(* Logix 5000 project; controller CompactLogix vendor 1 type 14 code 77 rev 13.15; software revision 13.03 *)

TASK MainTask (continuous, watchdog 500 ms) : MainProgram

MODULES
   Controller : vendor 1 type 14 code 77 (CompactLogixL32EController 0, rev 13.15)
      LocalENB : 1769-L32E Ethernet Port (CompactLogixL32Ethernet 1, Ethernet 192.168.10.210, rev 13.1)
      Local : CompactBus (CompactVirtualAdapter 3, rev 13.1, Input RPI 2 ms)
         DPM : 1769-MODULE (Compact 1, rev 1.1, Output RPI 2 ms)
END_MODULES

TYPE DDLM_GLOBAL_CONTROL_CONFIRM :
STRUCT
   Reserved1 : INT;
   Reserved2 : INT;
   Answer : SINT;
   Failure : SINT;
   Reserved3 : INT;
   DeviceAdr : SINT;
END_STRUCT
END_TYPE

TYPE DDLM_GLOBAL_CONTROL_REQUEST :
STRUCT
   Reserved1 : INT;
   Reserved2 : INT;
   Reserved3 : INT;
   Command : SINT;
   Reserved4 : SINT;
   DeviceAdr : SINT;
   ConrolCommand : SINT;
   GroupSelect : SINT;
END_STRUCT
END_TYPE

TYPE DDLM_SET_PARAMETER_CONFIRM :
STRUCT
   Reserved1 : INT;
   Reserved2 : INT;
   Answer : SINT;
   Failure : SINT;
   Reserved3 : INT;
   DeviceAdr : SINT;
END_STRUCT
END_TYPE

TYPE DDLM_SET_PARAMETER_REQUEST :
STRUCT
   Reserved1 : INT;
   Reserved2 : INT;
   Reserved3 : INT;
   Command : SINT;
   Reserved4 : SINT;
   UsrPrm : SINT[234];
END_STRUCT
END_TYPE

TYPE DDLM_SLAVE_DIAGNOSTIC_CONFIRM :
STRUCT
   Reserved1 : INT;
   Reserved2 : INT;
   Answer : SINT;
   Failure : SINT;
   Reserved3 : INT;
   DeviceAdr : SINT;
   DataArea : SINT;
   DataAdr : INT;
   DataIdx : SINT;
   DataCnt : SINT;
   DataType : SINT;
   Function : SINT;
   StationState_1 : SINT;
   StationState_2 : SINT;
   StationState_3 : SINT;
   MasterAddress : SINT;
   IdentNumber : INT;
   Reserved4 : INT;
   ExtDiag : SINT[100];
END_STRUCT
END_TYPE

TYPE DDLM_SLAVE_DIAGNOSTIC_REQUEST :
STRUCT
   Reserved1 : INT;
   Reserved2 : INT;
   Reserved3 : INT;
   Command : SINT;
   Reserved4 : SINT;
   DeviceAdr : SINT;
   DataArea : SINT;
   DataAdr : INT;
   DataIdx : SINT;
   DataCnt : SINT;
   DataType : SINT;
   Function : SINT;
END_STRUCT
END_TYPE

TYPE DPM_DEV_COMMAND_REGISTER :   // Device Command Register
STRUCT
   Reserved0 : BOOL;   // Reserved
   Reserved1 : BOOL;   // Reserved
   Reserved2 : BOOL;   // Reserved
   Reserved3 : BOOL;   // Reserved
   Reserved4 : BOOL;   // Reserved
   NRdy : BOOL;   // Application Not Ready
   Init : BOOL;   // Init ( Warm boot )
   Reset : BOOL;   // Reset ( Cold boot )
   HsReq0 : BOOL;   // Slave Diag Request
   HsReq1 : BOOL;   // Global Control Request
   HsReq2 : BOOL;   // Reserved
   HsReq3 : BOOL;   // Reserved
   HsReq4 : BOOL;   // Reserved
   HsReq5 : BOOL;   // Reserved
   HsReq6 : BOOL;   // Reserved
   HsReq7 : BOOL;   // Reserved
   Reserved5 : SINT;   // Reserved
   Reserved6 : SINT;   // Reserved
END_STRUCT
END_TYPE

TYPE DPM_DEV_STATUS_REGISTER :   // Device Status Register
STRUCT
   Reserved0 : BOOL;
   Reserved1 : BOOL;
   Reserved2 : BOOL;
   Reserved3 : BOOL;
   Reserved4 : BOOL;
   Com : BOOL;   // Communication
   Run : BOOL;   // Running
   Rdy : BOOL;   // Ready
   HsAck0 : BOOL;   // Slave Diag Acknowledge
   HsAck1 : BOOL;   // Global Control Acknowledge
   HsAck2 : BOOL;
   HsAck3 : BOOL;
   HsAck4 : BOOL;
   HsAck5 : BOOL;
   HsAck6 : BOOL;
   HsAck7 : BOOL;
   Reserved5 : SINT;
   Reserved6 : SINT;
END_STRUCT
END_TYPE

TYPE DPM_DPV1_ALARM_INDICATION :   // DPV1 Alarm Indication
STRUCT
   AlarmIndication : BOOL;   // Indicates an alarm
   Reserved1 : BOOL;
   Reserved2 : BOOL;
   Reserved3 : BOOL;
   Reserved4 : BOOL;
   Reserved5 : BOOL;
   Reserved6 : BOOL;
   AlarmOverrun : BOOL;   // Overflow of the modules internal alarm buffer
   AlarmCnt : SINT;   // Alarm indication counter
   RemoteAddress : SINT;   // Address of Slave with Alarm
   Slot : SINT;   // Slot Number
   Sequence : SINT;   // Sequence Number
   AlarmType : SINT;   // Alarm Type
   AlarmSpec : SINT;   // Alarm Specification
   Reserved7 : SINT;
END_STRUCT
END_TYPE

TYPE DPM_FW_REVISION :   // Firmware Major/Minor Revision
STRUCT
   FwMinor : SINT;   // Firmware Minor Revison
   FwMajor : SINT;   // Firmware Major Revison
   Reserved : INT;   // Reserved
END_STRUCT
END_TYPE

TYPE DPM_GLOBAL_CONTROL_COMMAND :   // Global Control Command
STRUCT
   SlaveAddress : SINT;   // Slave Address
   ControlCommand : SINT;   // Control Command to be send
   GroupSelect : SINT;   // Group Select
   Reserved1 : SINT;
END_STRUCT
END_TYPE

TYPE DPM_GLOBAL_STATE_FIELD :   // PROFIBUS Master Global State Field
STRUCT
   Ctrl : BOOL;   // Control error
   Aclr : BOOL;   // Auto clear error
   Nexc : BOOL;   // Non exchange error
   Fat : BOOL;   // Fatal error
   Eve : BOOL;   // Event error
   NRdy : BOOL;   // Host not ready notification
   Tout : BOOL;   // Timeout
   Reserved1 : BOOL;   // Reserved
   DPM_State : SINT;   // Master main state
   Err_rem_adr : SINT;   // Faulty remote address
   Err_event : SINT;   // Error Number
   Bus_err_cnt : INT;   // Heavy bus error counter
   Time_out_cnt : INT;   // Number of rejected PROFIBUS Telegr.
   Reserved : SINT[8];   // Reserved
   Sl_cfg : BOOL[128];   // Slave Config
   Sl_state : BOOL[128];   // Slave State
   Sl_diag : BOOL[128];   // Slave Diag
END_STRUCT
END_TYPE

TYPE DPM_INPUT_ARRAY :
STRUCT
   DevStaReg : DPM_DEV_STATUS_REGISTER;
   FwRev : DPM_FW_REVISION;
   GlobStateField : DPM_GLOBAL_STATE_FIELD;
   SlaveDiag : DPM_SLAVE_DIAG_DATA;
   AlarmInd : DPM_DPV1_ALARM_INDICATION;
   InputData : SINT[408];   // PROFIBUS Input data.
END_STRUCT
END_TYPE

TYPE DPM_OUTPUT_ARRAY :
STRUCT
   DevCmdReg : DPM_DEV_COMMAND_REGISTER;
   DiagReqAdr : DPM_SLAVE_DIAG_COMMAND;
   GlobCtrl : DPM_GLOBAL_CONTROL_COMMAND;
   Reserved : SINT[4];
   OutputData : SINT[480];   // PROFIBUS Output data.
END_STRUCT
END_TYPE

TYPE DPM_SLAVE_DIAG_COMMAND :   // Requested address for SlaveDiagnostics
STRUCT
   SlaveAddress : SINT;
   DiagMode : SINT;
   Reserved1 : SINT;
   Reserved2 : SINT;
END_STRUCT
END_TYPE

TYPE DPM_SLAVE_DIAG_DATA :   // Slave standard diagnostic data according to PROFIBUS norm.
STRUCT
   SlaveAddress : SINT;   // Slave address
   DiagFailure : SINT;   // Slave Diag Failure
   Sta1_StationNotExist : BOOL;   // No response
   Sta1_StationNotReady : BOOL;   // Station not ready
   Sta1_CfgFault : BOOL;   // Configuration faulty
   Sta1_ExtDiag : BOOL;   // Extended diagnostic
   Sta1_NotSupp : BOOL;   // Sync,Freeze not supported
   Sta1_InvalidResponse : BOOL;   // Response faulty
   Sta1_PrmFault : BOOL;   // Parameters faulty
   Sta1_MasterLock : BOOL;   // Locked by a master
   Sta2_PrmReq : BOOL;   // Request new parameter
   Sta2_StatDiag : BOOL;   // Static diagnostic
   Sta2_Slave : BOOL;   // Set to 1 by a slave
   Sta2_Watchdog : BOOL;   // Watchdog ON/OFF
   Sta2_FreezeMode : BOOL;   // Freeze mode active
   Sta2_SyncMode : BOOL;   // Sync mode active
   Sta2_Reserved : BOOL;   // Reserved
   Sta2_Deactivated : BOOL;   // Slave deactivated
   Sta3_Reserved0 : BOOL;   // Reserved
   Sta3_Reserved1 : BOOL;   // Reserved
   Sta3_Reserved2 : BOOL;   // Reserved
   Sta3_Reserved3 : BOOL;   // Reserved
   Sta3_Reserved4 : BOOL;   // Reserved
   Sta3_Reserved5 : BOOL;   // Reserved
   Sta3_Reserved6 : BOOL;   // Reserved
   Sta3_ExtDiagOverflow : BOOL;   // Extended diagnostic overflow
   MasterAddress : SINT;   // Corresponding master address
   IdentNumber : INT;   // PROFIBUS Ident number
END_STRUCT
END_TYPE

TYPE MSAC1_READ_CONFIRM :   // DPV1 Read Confirmation
STRUCT
   Reserved1 : INT;
   Reserved2 : INT;
   Answer : SINT;
   Failure : SINT;
   Reserved3 : INT;
   DeciceAdr : SINT;
   DataArea : SINT;
   DataAdr : INT;
   DataIdx : SINT;
   DataCnt : SINT;
   DataType : SINT;
   Function : SINT;
   Data : SINT[240];
END_STRUCT
END_TYPE

TYPE MSAC1_READ_REQUEST :   // DPV1 Read Request
STRUCT
   Reserved1 : INT;
   Reserved2 : INT;
   Reserved3 : INT;
   Command : SINT;
   Reserved4 : SINT;
   DeviceAdr : SINT;
   DataArea : SINT;
   DataAdr : INT;
   DataIdx : SINT;
   DataCnt : SINT;
   DataType : SINT;
   Function : SINT;
END_STRUCT
END_TYPE

TYPE MSAC1_WRITE_CONFIRM :   // DPV1 Write Confirmation
STRUCT
   Reserved1 : INT;
   Reserved2 : INT;
   Answer : SINT;
   Failure : SINT;
   Reserved3 : INT;
   DeciceAdr : SINT;
   DataArea : SINT;
   DataAdr : INT;
   DataIdx : SINT;
   DataCnt : SINT;
   DataType : SINT;
   Function : SINT;
   ErrorCode1 : SINT;
   ErrorCode2 : SINT;
END_STRUCT
END_TYPE

TYPE MSAC1_WRITE_REQUEST :   // DPV1 Write Request
STRUCT
   Reserved1 : INT;
   Reserved2 : INT;
   Reserved3 : INT;
   Command : SINT;
   Reserved4 : SINT;
   DeviceAdr : SINT;
   DataArea : SINT;
   DataAdr : INT;
   DataIdx : SINT;
   DataCnt : SINT;
   DataType : SINT;
   Function : SINT;
   data : SINT[240];
END_STRUCT
END_TYPE

TYPE MSAL1M_ALARM_CONFIRM :
STRUCT
   Reserved1 : INT;
   Reserved2 : INT;
   Answer : SINT;
   Failure : SINT;
   Reserved3 : INT;
   SlaveAdr : SINT;
   SlotNum : SINT;
   SeqNum : SINT;
   AlarmType : SINT;
   AlarmSpec : SINT;
   Reserved4 : SINT;
END_STRUCT
END_TYPE

TYPE MSAL1M_ALARM_RESPONSE :
STRUCT
   Reserved1 : INT;
   Reserved2 : INT;
   Reserved3 : INT;
   Command : SINT;
   Reserved4 : SINT;
   SlaveAdr : SINT;
   SlotNum : SINT;
   SeqNum : SINT;
   AlarmType : SINT;
   AlarmSpec : SINT;
   Reserved5 : SINT;
END_STRUCT
END_TYPE

VAR_GLOBAL   (* controller tags *)
   AlarmCnf : MSAL1M_ALARM_CONFIRM := (Answer := 18, SlaveAdr := 2, SlotNum := -122, SeqNum := 6, AlarmType := 59, AlarmSpec := 6);
   AlarmIndCounter : SINT;
   AlarmReceiveCounter : INT;   // Alarm Counter
   AlarmResErr : BOOL;
   AlarmRsp : MSAL1M_ALARM_RESPONSE := (Command := 18);
   AlarmRspMsg : MESSAGE;   // Alarm Response Message
        MessageParameters(ServiceCode := 16#0064, LocalElement := AlarmRsp, DestinationTag := AlarmCnf, ...)
   DoDDLMGlblCtrl : BOOL;
   DoDDLMSetPrm : BOOL;
   DoDDLMSlaveDiag : BOOL;
   DoDPV1AlarmRsp : BOOL;
   DoDPV1ReadReq : BOOL;
   DoDPV1WriteReq : BOOL;
   DpmInputArray : DPM_INPUT_ARRAY;
   DpmOutputArray : DPM_OUTPUT_ARRAY;
   GlbCtrlCnf : DDLM_GLOBAL_CONTROL_CONFIRM := (Answer := 70, DeviceAdr := 2);   // Global Control Confirmation
   GlbCtrlMsg : MESSAGE;   // Global Control Message
        MessageParameters(ServiceCode := 16#0064, LocalElement := GlbCtrlReq, DestinationTag := GlbCtrlCnf, ...)
   GlbCtrlReq : DDLM_GLOBAL_CONTROL_REQUEST := (Command := 70, DeviceAdr := 2, ConrolCommand := 2#0000_1000);   // Global Control Request
        .COMMAND   // Global Control Request
   MainInitDone : BOOL;
   ReadCnf : MSAC1_READ_CONFIRM := (Answer := 17, DeciceAdr := 2, DataAdr := 1, DataIdx := 1, DataCnt := 2, DataType := 10, Function := 1, Data[0] := 1, Data[1] := 2);   // Read Confimation
   ReadReq : MSAC1_READ_REQUEST := (Command := 17, DeviceAdr := 2, DataAdr := 1, DataIdx := 1, DataCnt := 2, DataType := 10, Function := 1);   // Read Request
   ReadReqMsg : MESSAGE;   // Slave Read Request Message
        .EN   // Slave Read Request Message
        MessageParameters(ServiceCode := 16#0064, LocalElement := ReadReq, DestinationTag := ReadCnf, ...)
   SetPrmCnf : DDLM_SET_PARAMETER_CONFIRM := (Answer := 74, DeviceAdr := 2);   // Set parameter confirmation
   SetPrmReq : DDLM_SET_PARAMETER_REQUEST := (Command := 74, UsrPrm[0] := 2);   // Set parameter request
   SetPrmReqMsg : MESSAGE;
        MessageParameters(ServiceCode := 16#0064, LocalElement := SetPrmReq, DestinationTag := SetPrmCnf, ...)
   SlaveAddress : SINT;   // Slave address used by several CIP messages
   SlaveDiagCnf : DDLM_SLAVE_DIAGNOSTIC_CONFIRM := (Answer := 66, DeviceAdr := 2, DataCnt := 6, Function := 1, StationState_1 := 2#0000_1000, StationState_2 := 2#0000_1100, MasterAddress := 1, IdentNumber := 16#0475, ExtDiag[0] := 18, ExtDiag[1] := 59, ExtDiag[2] := -122, ExtDiag[3] := 54, ExtDiag[4] := 77, ExtDiag[5] := 65, ExtDiag[6] := 89, ExtDiag[7] := 68, ExtDiag[8] := 65, ExtDiag[9] := 89, ExtDiag[10] := 44, ExtDiag[11] := 32, ExtDiag[12] := 77, ExtDiag[13] := 65, ExtDiag[14] := 89, ExtDiag[15] := 68, ExtDiag[16] := 65, ExtDiag[17] := 89);   // Slave Diag Confirmation
   SlaveDiagMsg : MESSAGE;   // Slave Diag Message
        .EN   // Slave Diag Message
        MessageParameters(ServiceCode := 16#0064, LocalElement := SlaveDiagReq, DestinationTag := SlaveDiagCnf, ...)
   SlaveDiagReq : DDLM_SLAVE_DIAGNOSTIC_REQUEST := (Command := 66, DeviceAdr := 2, Function := 1);   // Slave Diag Request
   WriteCnf : MSAC1_WRITE_CONFIRM := (Answer := 17, DeciceAdr := 2, DataAdr := 1, DataIdx := 1, DataCnt := 2, DataType := 10, Function := 2);   // Slave Write Confirmation
   WriteReq : MSAC1_WRITE_REQUEST := (Command := 17, DeviceAdr := 2, DataAdr := 1, DataIdx := 1, DataCnt := 2, DataType := 10, Function := 2, data[0] := 85, data[1] := 17);   // Slave Write Request
   WriteReqMsg : MESSAGE;   // Slave Write Request Message
        .EN   // Slave Write Request Message
        MessageParameters(ServiceCode := 16#0064, LocalElement := WriteReq, DestinationTag := WriteCnf, ...)
END_VAR

PROGRAM MainProgram   (* routine attr 65 MainRoutine *)

ROUTINE AlarmHandler   (* ladder *)
// Alarm Handler
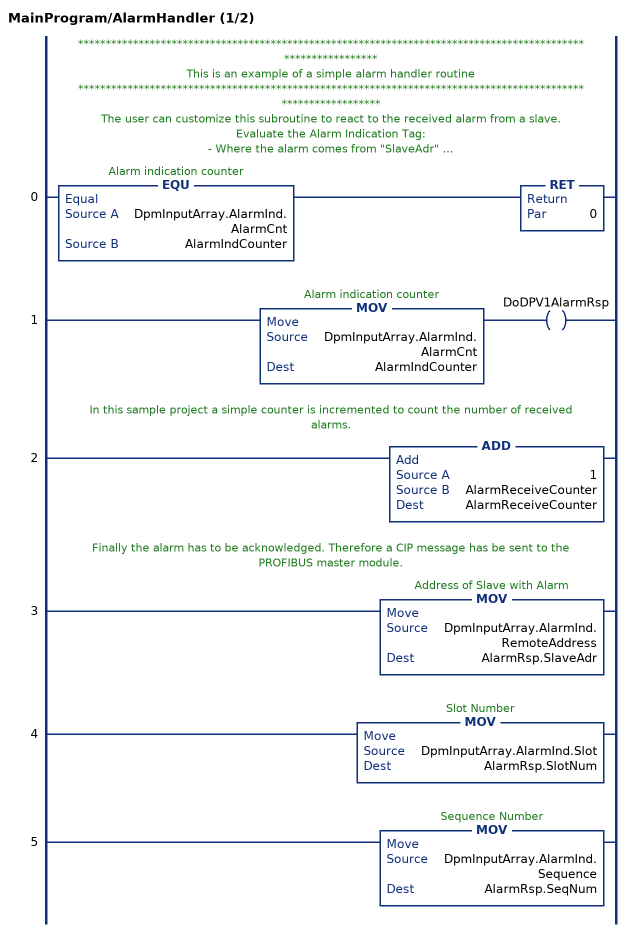
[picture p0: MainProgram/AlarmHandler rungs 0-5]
   // *************************************************************************************************************
   // This is an example of a simple alarm handler routine
   // **************************************************************************************************************
   // The user can customize this subroutine to react to the received alarm from a slave.
   // Evaluate the Alarm Indication Tag:
   //  - Where the alarm comes from "SlaveAdr" ?
   // -  What kind of alarm is it  "AlarmType" ?
   // ect. ....
   0: EQU(DpmInputArray.AlarmInd.AlarmCnt,AlarmIndCounter)RET(0);
   1: MOV(DpmInputArray.AlarmInd.AlarmCnt,AlarmIndCounter)OTE(DoDPV1AlarmRsp);
   // In this sample project a simple counter is incremented to count the number of received alarms.
   2: ADD(1,AlarmReceiveCounter,AlarmReceiveCounter);
   // Finally the alarm has to be acknowledged. Therefore a CIP message has be sent to the PROFIBUS master module.
   3: MOV(DpmInputArray.AlarmInd.RemoteAddress,AlarmRsp.SlaveAdr);
   4: MOV(DpmInputArray.AlarmInd.Slot,AlarmRsp.SlotNum);
   5: MOV(DpmInputArray.AlarmInd.Sequence,AlarmRsp.SeqNum);
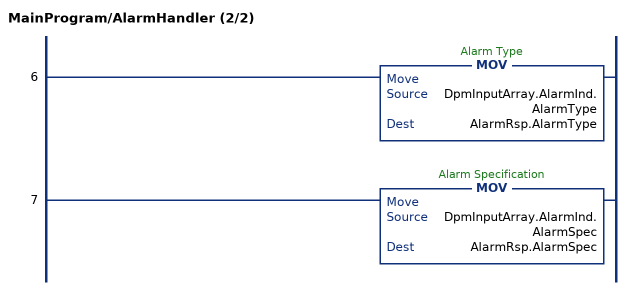
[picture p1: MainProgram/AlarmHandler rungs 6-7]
   6: MOV(DpmInputArray.AlarmInd.AlarmType,AlarmRsp.AlarmType);
   7: MOV(DpmInputArray.AlarmInd.AlarmSpec,AlarmRsp.AlarmSpec);
END_ROUTINE

ROUTINE Init_AlarmResMsg   (* ladder *)
// Init Alarm Response Message
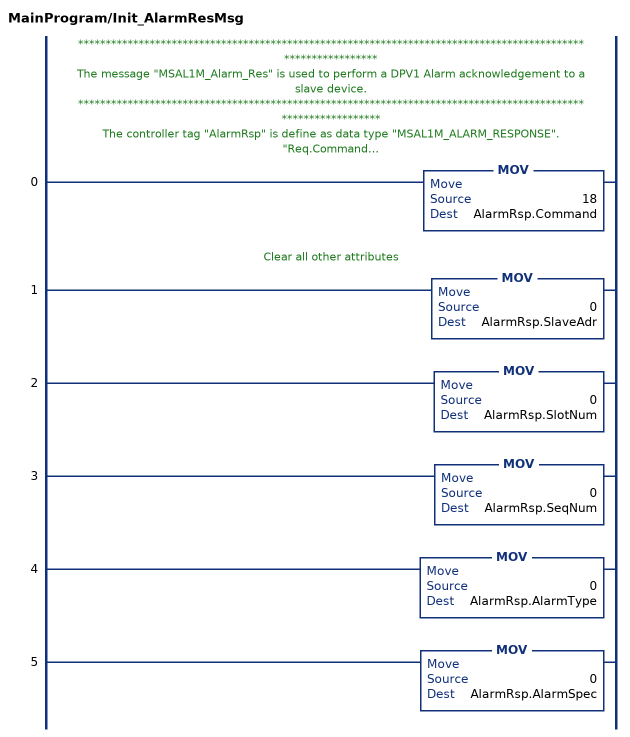
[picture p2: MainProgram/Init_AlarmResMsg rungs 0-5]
   // *************************************************************************************************************
   // The message "MSAL1M_Alarm_Res" is used to perform a DPV1 Alarm acknowledgement to a slave device.
   // **************************************************************************************************************
   // The controller tag "AlarmRsp" is define as data type "MSAL1M_ALARM_RESPONSE".
   // "Req.Command"
   // Setup "Req.Command" to 18. This is the command for "MSAL1M_Alarm_Res".
   0: MOV(18,AlarmRsp.Command);
   // Clear all other attributes
   1: MOV(0,AlarmRsp.SlaveAdr);
   2: MOV(0,AlarmRsp.SlotNum);
   3: MOV(0,AlarmRsp.SeqNum);
   4: MOV(0,AlarmRsp.AlarmType);
   5: MOV(0,AlarmRsp.AlarmSpec);
END_ROUTINE

ROUTINE Init_GlobalControlMsg   (* ladder *)
// Init Global Control Message
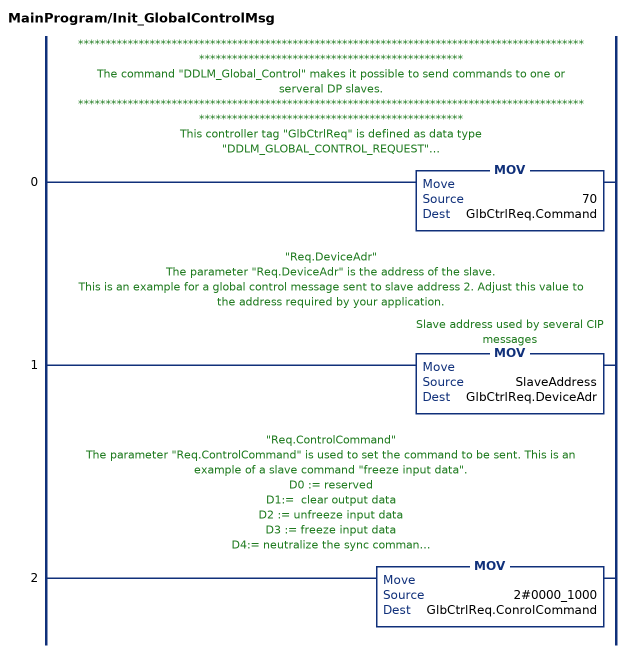
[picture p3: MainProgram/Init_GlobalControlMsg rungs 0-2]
   // ********************************************************************************************************************************************
   // The command "DDLM_Global_Control" makes it possible to send commands to one or serveral DP slaves.
   // ********************************************************************************************************************************************
   // This controller tag "GlbCtrlReq" is defined as data type "DDLM_GLOBAL_CONTROL_REQUEST".
   // "Req.Command"
   // Setup "Req.Command" to 70. This is the command for "DDLM_Global_Control".
   0: MOV(70,GlbCtrlReq.Command);
   // "Req.DeviceAdr"
   // The parameter "Req.DeviceAdr" is the address of the slave.
   // This is an example for a global control message sent to slave address 2. Adjust this value to the address required by your application.
   1: MOV(SlaveAddress,GlbCtrlReq.DeviceAdr);
   // "Req.ControlCommand"
   // The parameter "Req.ControlCommand" is used to set the command to be sent. This is an example of a slave command "freeze input data".
   // D0 := reserved
   // D1:=  clear output data
   // D2 := unfreeze input data
   // D3 := freeze input data
   // D4:= neutralize the sync command
   // D5 := freeze output data, till sync command is canceled
   // D6 := reserved
   // D7 := reserved
   2: MOV(2#0000_1000,GlbCtrlReq.ConrolCommand);
END_ROUTINE

ROUTINE Init_GlobalVariables   (* ladder *)
// Initialization of global variables which are used in several program parts
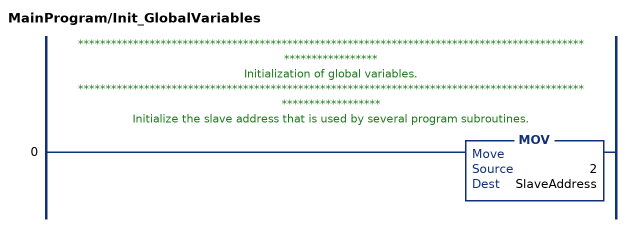
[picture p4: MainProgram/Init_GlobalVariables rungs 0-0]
   // *************************************************************************************************************
   // Initialization of global variables.
   // **************************************************************************************************************
   // Initialize the slave address that is used by several program subroutines.
   0: MOV(2,SlaveAddress);
END_ROUTINE

ROUTINE Init_ReadReqMsg   (* ladder *)
// Init Read Request Message
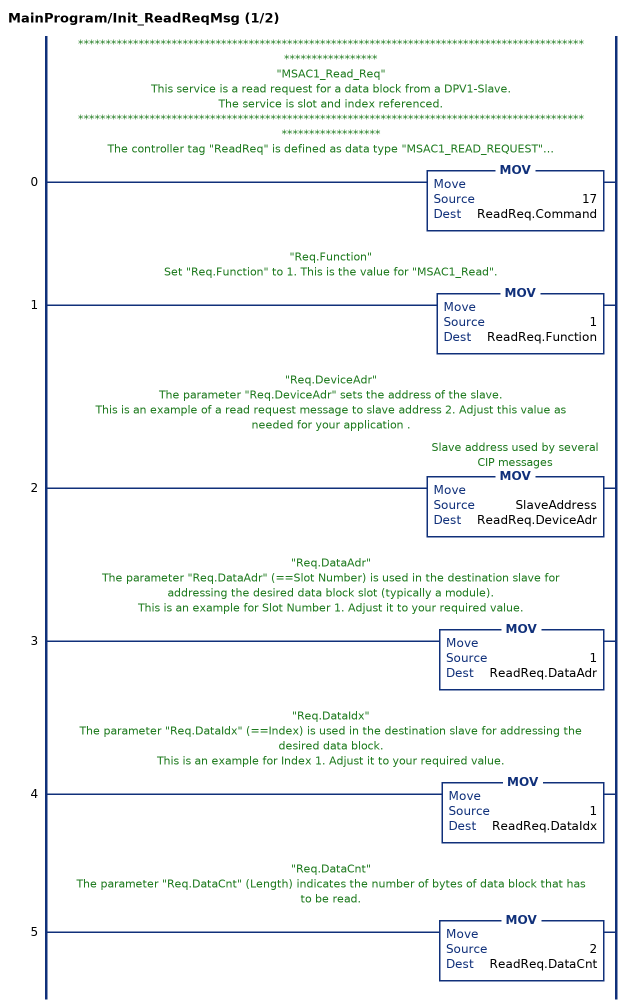
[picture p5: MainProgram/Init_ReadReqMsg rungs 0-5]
   // *************************************************************************************************************
   // "MSAC1_Read_Req"
   // This service is a read request for a data block from a DPV1-Slave.
   // The service is slot and index referenced.
   // **************************************************************************************************************
   // The controller tag "ReadReq" is defined as data type "MSAC1_READ_REQUEST".
   // "Req.Command"
   // Set "Req.Command" to 17. This is the command for "MSAC1_Read" and  "MSAC1_Write
   0: MOV(17,ReadReq.Command);
   // "Req.Function"
   // Set "Req.Function" to 1. This is the value for "MSAC1_Read".
   1: MOV(1,ReadReq.Function);
   // "Req.DeviceAdr"
   // The parameter "Req.DeviceAdr" sets the address of the slave.
   // This is an example of a read request message to slave address 2. Adjust this value as needed for your application .
   2: MOV(SlaveAddress,ReadReq.DeviceAdr);
   // "Req.DataAdr"
   // The parameter "Req.DataAdr" (==Slot Number) is used in the destination slave for addressing the desired data block slot (typically a module).
   // This is an example for Slot Number 1. Adjust it to your required value.
   3: MOV(1,ReadReq.DataAdr);
   // "Req.DataIdx"
   // The parameter "Req.DataIdx" (==Index) is used in the destination slave for addressing the desired data block.
   // This is an example for Index 1. Adjust it to your required value.
   4: MOV(1,ReadReq.DataIdx);
   // "Req.DataCnt"
   // The parameter "Req.DataCnt" (Length) indicates the number of bytes of data block that has to be read.
   5: MOV(2,ReadReq.DataCnt);
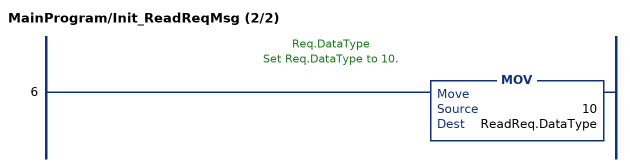
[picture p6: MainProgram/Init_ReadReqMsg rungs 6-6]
   // Req.DataType
   // Set Req.DataType to 10.
   6: MOV(10,ReadReq.DataType);
END_ROUTINE

ROUTINE Init_SetParameterMsg   (* ladder *)
// Init Set Parameter Message
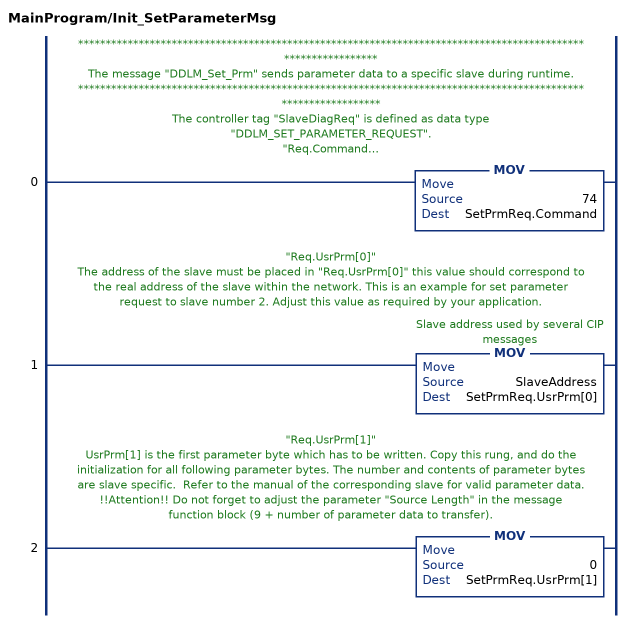
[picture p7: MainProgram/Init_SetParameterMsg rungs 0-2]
   // *************************************************************************************************************
   // The message "DDLM_Set_Prm" sends parameter data to a specific slave during runtime.
   // **************************************************************************************************************
   // The controller tag "SlaveDiagReq" is defined as data type "DDLM_SET_PARAMETER_REQUEST".
   // "Req.Command"
   // Set "Req.Command" to 74. This is the command for "DDLM_Set_Prm"
   0: MOV(74,SetPrmReq.Command);
   // "Req.UsrPrm[0]"
   // The address of the slave must be placed in "Req.UsrPrm[0]" this value should correspond to the real address of the slave within the network. This is an example for set parameter request to slave number 2. Adjust this value as required by your application.
   1: MOV(SlaveAddress,SetPrmReq.UsrPrm[0]);
   // "Req.UsrPrm[1]"
   // UsrPrm[1] is the first parameter byte which has to be written. Copy this rung, and do the initialization for all following parameter bytes. The number and contents of parameter bytes are slave specific.  Refer to the manual of the corresponding slave for valid parameter data.
   // !!Attention!! Do not forget to adjust the parameter "Source Length" in the message function block (9 + number of parameter data to transfer).
   2: MOV(0,SetPrmReq.UsrPrm[1]);
END_ROUTINE

ROUTINE Init_SlaveDiagMsg   (* ladder *)
// Init Slave Diag Message
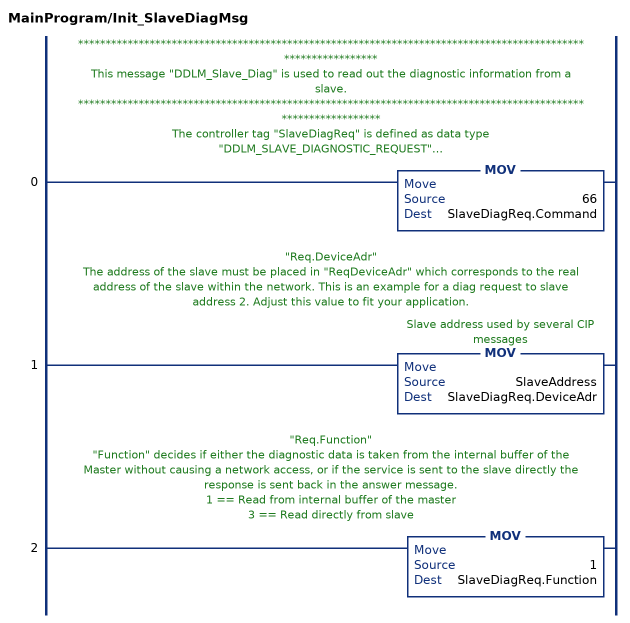
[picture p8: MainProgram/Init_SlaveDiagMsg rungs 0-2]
   // *************************************************************************************************************
   // This message "DDLM_Slave_Diag" is used to read out the diagnostic information from a slave.
   // **************************************************************************************************************
   // The controller tag "SlaveDiagReq" is defined as data type "DDLM_SLAVE_DIAGNOSTIC_REQUEST".
   // "Req.Command"
   // Set "Req.Command" to 66. This is the command for "DDLM_Slave_Dialg"
   0: MOV(66,SlaveDiagReq.Command);
   // "Req.DeviceAdr"
   // The address of the slave must be placed in "ReqDeviceAdr" which corresponds to the real address of the slave within the network. This is an example for a diag request to slave address 2. Adjust this value to fit your application.
   1: MOV(SlaveAddress,SlaveDiagReq.DeviceAdr);
   // "Req.Function"
   // "Function" decides if either the diagnostic data is taken from the internal buffer of the Master without causing a network access, or if the service is sent to the slave directly the response is sent back in the answer message.
   // 1 == Read from internal buffer of the master
   // 3 == Read directly from slave
   2: MOV(1,SlaveDiagReq.Function);
END_ROUTINE

ROUTINE Init_WriteReqMsg   (* ladder *)
// Init Write Request Message
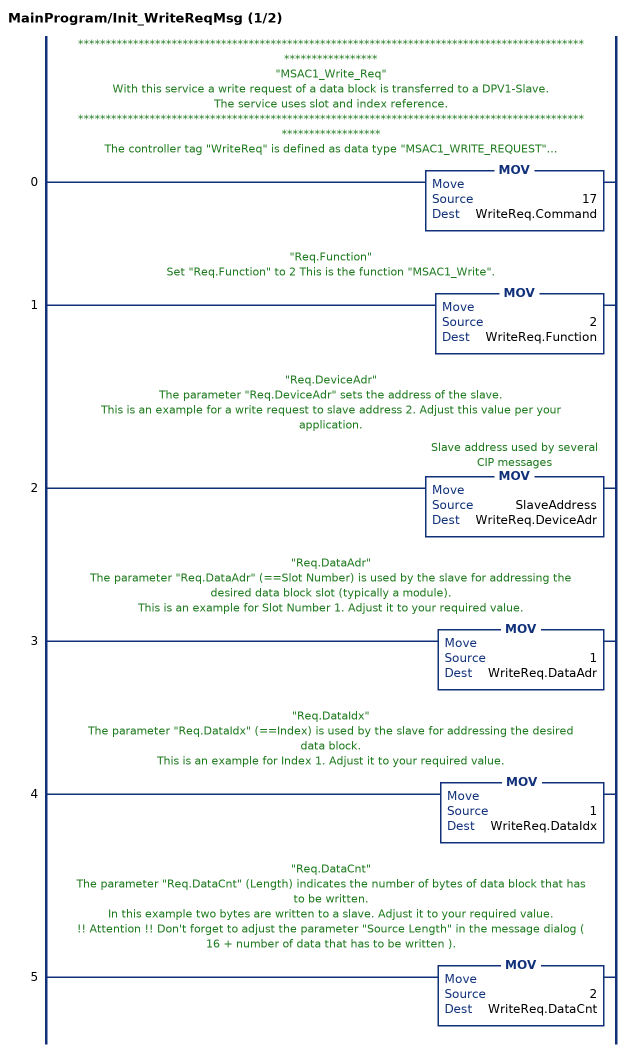
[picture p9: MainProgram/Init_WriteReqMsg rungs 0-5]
   // *************************************************************************************************************
   // "MSAC1_Write_Req"
   // With this service a write request of a data block is transferred to a DPV1-Slave.
   // The service uses slot and index reference.
   // **************************************************************************************************************
   // The controller tag "WriteReq" is defined as data type "MSAC1_WRITE_REQUEST".
   // "Req.Command"
   // Set "Req.Command" to 17. This is the command for "MSAC1_Write" and  "MSAC1_Read".
   0: MOV(17,WriteReq.Command);
   // "Req.Function"
   // Set "Req.Function" to 2 This is the function "MSAC1_Write".
   1: MOV(2,WriteReq.Function);
   // "Req.DeviceAdr"
   // The parameter "Req.DeviceAdr" sets the address of the slave.
   // This is an example for a write request to slave address 2. Adjust this value per your application.
   2: MOV(SlaveAddress,WriteReq.DeviceAdr);
   // "Req.DataAdr"
   // The parameter "Req.DataAdr" (==Slot Number) is used by the slave for addressing the desired data block slot (typically a module).
   // This is an example for Slot Number 1. Adjust it to your required value.
   3: MOV(1,WriteReq.DataAdr);
   // "Req.DataIdx"
   // The parameter "Req.DataIdx" (==Index) is used by the slave for addressing the desired data block.
   // This is an example for Index 1. Adjust it to your required value.
   4: MOV(1,WriteReq.DataIdx);
   // "Req.DataCnt"
   // The parameter "Req.DataCnt" (Length) indicates the number of bytes of data block that has to be written.
   // In this example two bytes are written to a slave. Adjust it to your required value.
   // !! Attention !! Don't forget to adjust the parameter "Source Length" in the message dialog ( 16 + number of data that has to be written ).
   5: MOV(2,WriteReq.DataCnt);
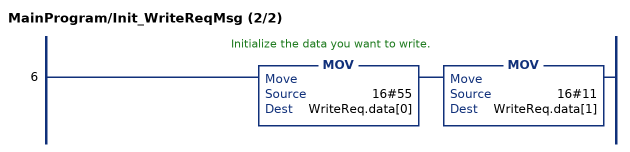
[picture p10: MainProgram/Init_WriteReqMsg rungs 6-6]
   // Initialize the data you want to write.
   6: MOV(16#55,WriteReq.data[0])MOV(16#11,WriteReq.data[1]);
END_ROUTINE

ROUTINE MainRoutine   (* ladder *)
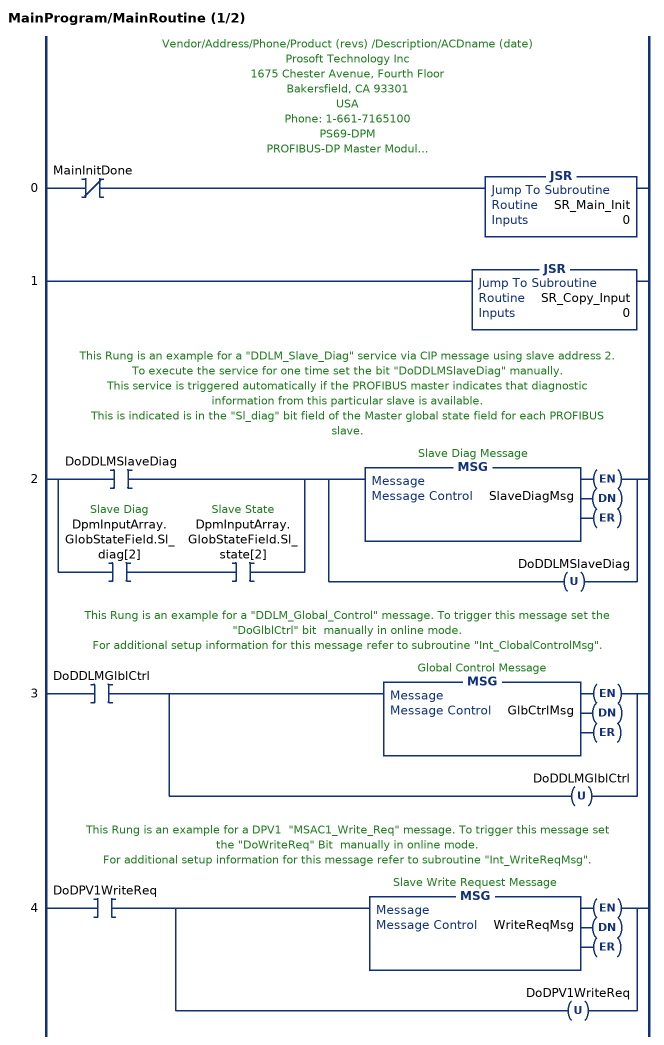
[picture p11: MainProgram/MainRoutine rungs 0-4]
   // Vendor/Address/Phone/Product (revs) /Description/ACDname (date)
   // Prosoft Technology Inc
   // 1675 Chester Avenue, Fourth Floor
   // Bakersfield, CA 93301
   // USA
   // Phone: 1-661-7165100
   // PS69-DPM
   // PROFIBUS-DP Master Module
   // PS69_DPM_messaging_L32E.ACD (Rev1.0) (07/28/05)
   // Although this program has been developed with great care and intensively tested,
   // Prosoft Technology Inc cannot guarantee the suitability of this program
   // for any purpose not confirmed by us in writing.
   // We reserve the right to modify our products and their specifications at any time in as far as this contributes to technical progress.
   // The version of the manual supplied with the program applies.
   // Guarantee claims shall be limited to the right to require rectification. Liability for any damages which may have arisen from the use of this program or its documentation shall be limited to cases of intent.
   // This program is a basic example RSLogix5000 project used for sending PROFIBUS messages to the communication module "PS69-DPM". This project provides an example for every supported PROFIBUS message by the module.
   // For detailed information about the these messages (functionality, parameters, error codes etc. ) refer to the module User Manual.
   // Rung 0 calls all init routines for one time, to initialize the PROFIBUS commands.
   0: XIO(MainInitDone)JSR(SR_Main_Init,0);
   1: JSR(SR_Copy_Input,0);
   // This Rung is an example for a "DDLM_Slave_Diag" service via CIP message using slave address 2.
   // To execute the service for one time set the bit "DoDDLMSlaveDiag" manually.
   // This service is triggered automatically if the PROFIBUS master indicates that diagnostic information from this particular slave is available.
   // This is indicated is in the "Sl_diag" bit field of the Master global state field for each PROFIBUS slave.
   2: [XIC(DoDDLMSlaveDiag) ,XIC(DpmInputArray.GlobStateField.Sl_diag[2]) XIC(DpmInputArray.GlobStateField.Sl_state[2]) ][MSG(SlaveDiagMsg) ,OTU(DoDDLMSlaveDiag) ];
   // This Rung is an example for a "DDLM_Global_Control" message. To trigger this message set the "DoGlblCtrl" bit  manually in online mode.
   // For additional setup information for this message refer to subroutine "Int_ClobalControlMsg".
   3: XIC(DoDDLMGlblCtrl)[MSG(GlbCtrlMsg) ,OTU(DoDDLMGlblCtrl) ];
   // This Rung is an example for a DPV1  "MSAC1_Write_Req" message. To trigger this message set the "DoWriteReq" Bit  manually in online mode.
   // For additional setup information for this message refer to subroutine "Int_WriteReqMsg".
   4: XIC(DoDPV1WriteReq)[MSG(WriteReqMsg) ,OTU(DoDPV1WriteReq) ];
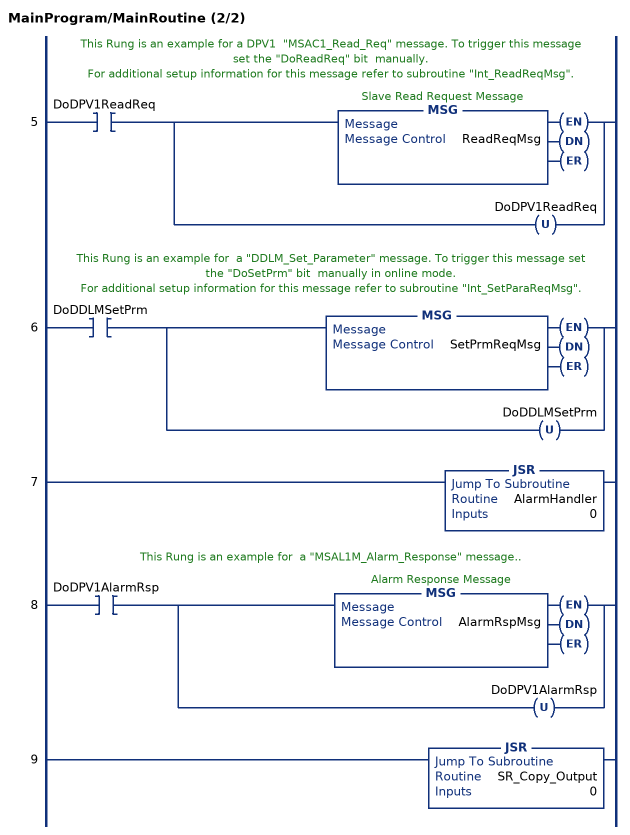
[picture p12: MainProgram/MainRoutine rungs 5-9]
   // This Rung is an example for a DPV1  "MSAC1_Read_Req" message. To trigger this message set the "DoReadReq" bit  manually.
   // For additional setup information for this message refer to subroutine "Int_ReadReqMsg".
   5: XIC(DoDPV1ReadReq)[MSG(ReadReqMsg) ,OTU(DoDPV1ReadReq) ];
   // This Rung is an example for  a "DDLM_Set_Parameter" message. To trigger this message set the "DoSetPrm" bit  manually in online mode.
   // For additional setup information for this message refer to subroutine "Int_SetParaReqMsg".
   6: XIC(DoDDLMSetPrm)[MSG(SetPrmReqMsg) ,OTU(DoDDLMSetPrm) ];
   7: JSR(AlarmHandler,0);
   // This Rung is an example for  a "MSAL1M_Alarm_Response" message..
   8: XIC(DoDPV1AlarmRsp)[MSG(AlarmRspMsg) ,OTU(DoDPV1AlarmRsp) ];
   9: JSR(SR_Copy_Output,0);
END_ROUTINE

ROUTINE SR_Copy_Input   (* ladder *)
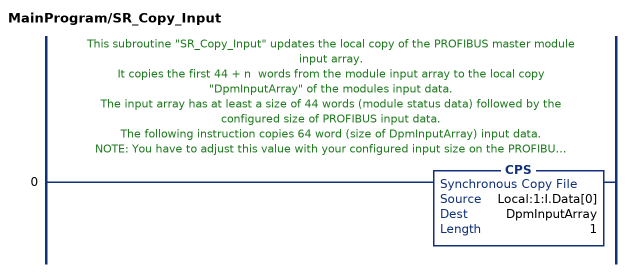
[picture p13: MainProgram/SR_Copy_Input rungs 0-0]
   // This subroutine "SR_Copy_Input" updates the local copy of the PROFIBUS master module input array.
   // It copies the first 44 + n  words from the module input array to the local copy "DpmInputArray" of the modules input data.
   // The input array has at least a size of 44 words (module status data) followed by the configured size of PROFIBUS input data.
   // The following instruction copies 64 word (size of DpmInputArray) input data.
   // NOTE: You have to adjust this value with your configured input size on the PROFIBUS network and the configured input size in the modules properties dialog Tab:General->Connection Paramter->Input.
   0: CPS(Local:1:I.Data[0],DpmInputArray,1);
END_ROUTINE

ROUTINE SR_Copy_Output   (* ladder *)
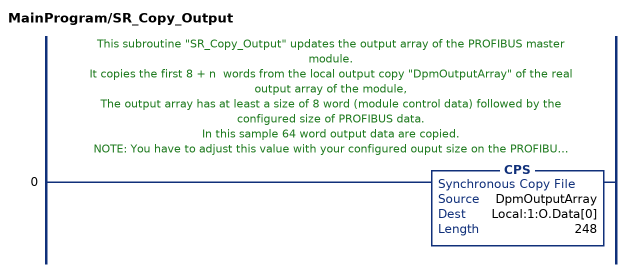
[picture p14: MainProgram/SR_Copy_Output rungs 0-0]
   // This subroutine "SR_Copy_Output" updates the output array of the PROFIBUS master module.
   // It copies the first 8 + n  words from the local output copy "DpmOutputArray" of the real output array of the module,
   // The output array has at least a size of 8 word (module control data) followed by the configured size of PROFIBUS data.
   // In this sample 64 word output data are copied.
   // NOTE: You have to adjust this value with your configured ouput size on the PROFIBUS network and the configured output size in the modules properties dialog Tab:General->Connection Paramter->Output.
   0: CPS(DpmOutputArray,Local:1:O.Data[0],248);
END_ROUTINE

ROUTINE SR_Main_Init   (* ladder *)
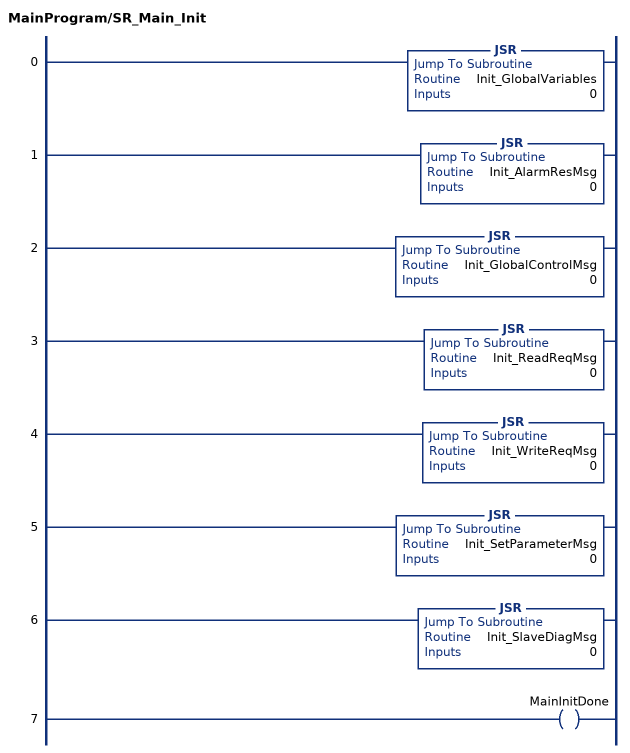
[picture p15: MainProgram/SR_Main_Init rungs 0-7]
   0: JSR(Init_GlobalVariables,0);
   1: JSR(Init_AlarmResMsg,0);
   2: JSR(Init_GlobalControlMsg,0);
   3: JSR(Init_ReadReqMsg,0);
   4: JSR(Init_WriteReqMsg,0);
   5: JSR(Init_SetParameterMsg,0);
   6: JSR(Init_SlaveDiagMsg,0);
   7: OTE(MainInitDone);
END_ROUTINE
END_PROGRAM
